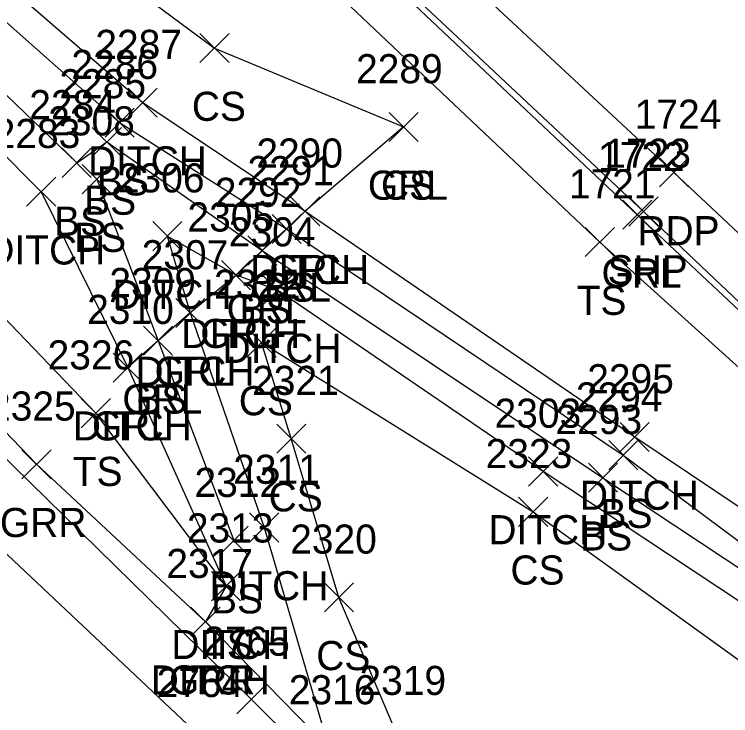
# Model space of a CAD drawing. Extents: x 1647574 to 1652703, y 212895 to 228670.
# Drawn here: x 1648670.85 to 1648720.04, y 227413.3 to 227461.47 of the extents above; entities that cross this region are included whole.
import ezdxf

# ---------------------------------------------------------------- set-up
doc = ezdxf.new("R2010")
doc.units = 0
for name, color, linetype in [('D_A', 7, 'Continuous'), ('D_I', 7, 'Continuous'), ('D_TIC', 7, 'Continuous'), ('DD', 7, 'Continuous'), ('L_A', 7, 'Continuous'), ('L_I', 7, 'Continuous'), ('L_TIC', 7, 'Continuous'), ('LELB', 7, 'Continuous'), ('P_A', 7, 'Continuous'), ('P_I', 7, 'Continuous'), ('P_TIC', 7, 'Continuous'), ('PET', 7, 'Continuous'), ('PSP', 7, 'Continuous'), ('R_A', 7, 'Continuous'), ('R_I', 7, 'Continuous'), ('R_TIC', 7, 'Continuous'), ('RGR', 7, 'Continuous')]:
    doc.layers.add(name, color=color, linetype=linetype)

msp = doc.modelspace()

# ---------------------------------------------------------------- linework, layer by layer
at = {"layer": 'D_TIC'}
for points in [[(1648678.668, 227454.407), (1648680.668, 227456.407)], [(1648680.668, 227454.407), (1648678.668, 227456.407)], [(1648671.688, 227448.29), (1648673.688, 227450.29)], [(1648673.688, 227448.29), (1648671.688, 227450.29)], [(1648689.817, 227446.944), (1648691.817, 227448.944)], [(1648691.817, 227446.944), (1648689.817, 227448.944)], [(1648680.354, 227445.239), (1648682.354, 227447.239)], [(1648682.354, 227445.239), (1648680.354, 227447.239)], [(1648685.075, 227442.554), (1648687.075, 227444.554)], [(1648687.075, 227442.554), (1648685.075, 227444.554)], [(1648687.91, 227441.53), (1648689.91, 227443.53)], [(1648689.91, 227441.53), (1648687.91, 227443.53)], [(1648681.932, 227439.96), (1648683.932, 227441.96)], [(1648683.932, 227439.96), (1648681.932, 227441.96)], [(1648677.631, 227436.205), (1648679.631, 227438.205)], [(1648679.631, 227436.205), (1648677.631, 227438.205)], [(1648712.453, 227431.442), (1648714.453, 227433.442)], [(1648714.453, 227431.442), (1648712.453, 227433.442)], [(1648706.167, 227429.076), (1648708.167, 227431.076)], [(1648708.167, 227429.076), (1648706.167, 227431.076)], [(1648687.005, 227425.227), (1648689.005, 227427.227)], [(1648689.005, 227425.227), (1648687.005, 227427.227)], [(1648684.391, 227421.196), (1648686.391, 227423.196)], [(1648686.391, 227421.196), (1648684.391, 227423.196)], [(1648682.979, 227418.757), (1648684.979, 227420.757)], [(1648684.979, 227418.757), (1648682.979, 227420.757)]]:
    msp.add_lwpolyline(points, dxfattribs=at)
at = {"layer": 'DD'}
for points in [[(1648567.346, 227553.333), (1648570.223, 227556.147), (1648596.039, 227533.3), (1648628.436, 227501.882), (1648658.018, 227474.124), (1648679.668, 227455.407), (1648690.817, 227447.944), (1648713.453, 227432.442), (1648744.751, 227411.459), (1648774.422, 227388.823), (1648782.608, 227379.999), (1648760.626, 227395.219), (1648734.749, 227411.807), (1648707.167, 227430.076), (1648688.91, 227442.53), (1648686.075, 227443.554), (1648681.354, 227446.239), (1648682.932, 227440.96), (1648688.005, 227426.227), (1648692.448, 227411.085)], [(1648567.346, 227553.333), (1648592.358, 227529.266), (1648624.337, 227498.311), (1648653.078, 227469.037), (1648672.688, 227449.29), (1648678.631, 227437.205), (1648685.391, 227422.196), (1648683.979, 227419.757)]]:
    msp.add_lwpolyline(points, dxfattribs=at)
at = {"layer": 'L_TIC'}
for points in [[(1648683.597, 227458.155), (1648685.597, 227460.155)], [(1648685.597, 227458.155), (1648683.597, 227460.155)], [(1648677.081, 227453.032), (1648679.081, 227455.032)], [(1648679.081, 227453.032), (1648677.081, 227455.032)], [(1648696.583, 227452.736), (1648698.583, 227454.736)], [(1648698.583, 227452.736), (1648696.583, 227454.736)], [(1648676.203, 227451.705), (1648678.203, 227453.705)], [(1648678.203, 227451.705), (1648676.203, 227453.705)], [(1648674.133, 227450.269), (1648676.133, 227452.269)], [(1648676.133, 227450.269), (1648674.133, 227452.269)], [(1648675.513, 227449.153), (1648677.513, 227451.153)], [(1648677.513, 227449.153), (1648675.513, 227451.153)], [(1648688.549, 227445.733), (1648690.549, 227447.733)], [(1648690.549, 227445.733), (1648688.549, 227447.733)], [(1648710.057, 227444.83), (1648712.057, 227446.83)], [(1648712.057, 227444.83), (1648710.057, 227446.83)], [(1648686.877, 227444.247), (1648688.877, 227446.247)], [(1648688.877, 227444.247), (1648686.877, 227446.247)], [(1648679.72, 227438.051), (1648681.72, 227440.051)], [(1648681.72, 227438.051), (1648679.72, 227440.051)], [(1648686.821, 227437.933), (1648688.821, 227439.933)], [(1648688.821, 227437.933), (1648686.821, 227439.933)], [(1648675.448, 227433.079), (1648677.448, 227435.079)], [(1648677.448, 227433.079), (1648675.448, 227435.079)], [(1648688.87, 227431.33), (1648690.87, 227433.33)], [(1648690.87, 227431.33), (1648688.87, 227433.33)], [(1648711.668, 227430.195), (1648713.668, 227432.195)], [(1648713.668, 227430.195), (1648711.668, 227432.195)], [(1648710.27, 227428.646), (1648712.27, 227430.646)], [(1648712.27, 227428.646), (1648710.27, 227430.646)], [(1648705.478, 227426.306), (1648707.478, 227428.306)], [(1648707.478, 227426.306), (1648705.478, 227428.306)], [(1648684.914, 227424.325), (1648686.914, 227426.325)], [(1648686.914, 227424.325), (1648684.914, 227426.325)], [(1648684.391, 227421.196), (1648686.391, 227423.196)], [(1648686.391, 227421.196), (1648684.391, 227423.196)], [(1648692.14, 227420.43), (1648694.14, 227422.43)], [(1648694.14, 227420.43), (1648692.14, 227422.43)]]:
    msp.add_lwpolyline(points, dxfattribs=at)
at = {"layer": 'LELB'}
for points in [[(1648774.577, 227389.564), (1648743.287, 227416.755), (1648711.057, 227445.83), (1648678.904, 227476.26), (1648653.936, 227498.583), (1648629.183, 227520.51), (1648599.068, 227550.478), (1648561.985, 227586.585), (1648537.336, 227611.828), (1648495.696, 227652.566), (1648469.806, 227680.635), (1648438.579, 227713.563), (1648409.766, 227744.994), (1648382.958, 227775.491), (1648351.838, 227812.297), (1648319.028, 227851.854)], [(1648685.391, 227422.196), (1648676.448, 227434.079), (1648653.997, 227457.482), (1648622.43, 227483.579), (1648591.456, 227513.122), (1648558.407, 227543.243), (1648525.701, 227574.495), (1648490.449, 227607.705), (1648459.181, 227639.732), (1648423.291, 227671.042), (1648396.89, 227698.593), (1648372.199, 227720.929), (1648349.64, 227747.392), (1648318.233, 227770.206)], [(1648557.515, 227558.902), (1648564.968, 227553.432), (1648569.913, 227558.452), (1648580.441, 227553.074), (1648598.911, 227536.759), (1648632.178, 227504.926), (1648659.98, 227477.367), (1648684.597, 227459.155), (1648697.583, 227453.736)], [(1648570.861, 227553.404), (1648569.637, 227552.186), (1648593.381, 227530.425), (1648625.493, 227499.025), (1648654.222, 227471.402), (1648675.133, 227451.269), (1648677.203, 227452.705), (1648687.877, 227445.247), (1648711.27, 227429.646), (1648742.963, 227408.638)], [(1648570.861, 227553.404), (1648594.803, 227532.123), (1648627.677, 227501.196), (1648656.322, 227473.309), (1648678.081, 227454.032), (1648689.549, 227446.733), (1648712.668, 227431.195), (1648742.963, 227408.638), (1648773.62, 227388.353)], [(1648676.513, 227450.153), (1648680.72, 227439.051), (1648685.914, 227425.325)], [(1648700.712, 227406.969), (1648697.252, 227411.723), (1648693.14, 227421.43), (1648689.87, 227432.33), (1648687.821, 227438.933), (1648706.478, 227427.306), (1648726.383, 227412.975)]]:
    msp.add_lwpolyline(points, dxfattribs=at)
at = {"layer": 'P_TIC'}
for points in [[(1648715.148, 227449.613), (1648717.148, 227451.613)], [(1648717.148, 227449.613), (1648715.148, 227451.613)], [(1648713.056, 227446.93), (1648715.056, 227448.93)], [(1648715.056, 227446.93), (1648713.056, 227448.93)], [(1648686.125, 227413.419), (1648688.125, 227415.419)], [(1648688.125, 227413.419), (1648686.125, 227415.419)]]:
    msp.add_lwpolyline(points, dxfattribs=at)
at = {"layer": 'PET'}
for points in [[(1648813.954, 227358.936), (1648778.044, 227392.689), (1648747.288, 227421.365), (1648716.148, 227450.613), (1648683.895, 227480.61), (1648659.116, 227504.214), (1648636.134, 227525.988), (1648605.632, 227555.477), (1648567.945, 227592.707), (1648543.864, 227616.052), (1648502.527, 227657.191), (1648475.057, 227685.791), (1648444.587, 227717.742), (1648415.435, 227749.693), (1648388.572, 227780.052), (1648357.179, 227817.313), (1648324.353, 227856.66)], [(1648315.17, 227761.114), (1648349.65, 227728.181), (1648382.593, 227697.154), (1648419.403, 227663.054), (1648452.032, 227631.593), (1648489.191, 227596.807), (1648522.695, 227564.838), (1648552.349, 227536.571), (1648584.489, 227506.143), (1648616.974, 227475.478), (1648654.438, 227439.35), (1648683.934, 227411.58), (1648698.744, 227397.704)]]:
    msp.add_lwpolyline(points, dxfattribs=at)
at = {"layer": 'PSP'}
for points in [[(1648862.79, 227349.772), (1648859.77, 227350.009), (1648838.072, 227353.54), (1648813.954, 227358.936), (1648808.767, 227359.651), (1648801.068, 227367.015), (1648799.396, 227367.692), (1648775.507, 227390.23), (1648744.844, 227418.747), (1648714.056, 227447.93), (1648681.623, 227478.355), (1648656.942, 227501.721), (1648633.184, 227523.882), (1648602.918, 227552.912), (1648564.866, 227589.709), (1648540.519, 227613.531), (1648499.098, 227654.744), (1648471.892, 227682.443), (1648441.114, 227715.054), (1648412.287, 227746.761), (1648385.497, 227777.337), (1648354.021, 227814.189), (1648321.056, 227853.92)], [(1648318.358, 227763.007), (1648352.653, 227731.112), (1648385.571, 227699.762), (1648421.79, 227665.61), (1648455.437, 227633.903), (1648491.739, 227599.359), (1648525.609, 227567.102), (1648554.892, 227539.659), (1648587.899, 227508.735), (1648620.045, 227478.677), (1648657.864, 227443.097), (1648687.125, 227414.419), (1648699.803, 227401.852), (1648705.852, 227396.154)]]:
    msp.add_lwpolyline(points, dxfattribs=at)
at = {"layer": 'R_TIC'}
for points in [[(1648696.583, 227452.736), (1648698.583, 227454.736)], [(1648698.583, 227452.736), (1648696.583, 227454.736)], [(1648689.817, 227446.944), (1648691.817, 227448.944)], [(1648691.817, 227446.944), (1648689.817, 227448.944)], [(1648712.629, 227446.707), (1648714.629, 227448.707)], [(1648714.629, 227446.707), (1648712.629, 227448.707)], [(1648688.549, 227445.733), (1648690.549, 227447.733)], [(1648690.549, 227445.733), (1648688.549, 227447.733)], [(1648686.877, 227444.247), (1648688.877, 227446.247)], [(1648688.877, 227444.247), (1648686.877, 227446.247)], [(1648685.075, 227442.554), (1648687.075, 227444.554)], [(1648687.075, 227442.554), (1648685.075, 227444.554)], [(1648681.932, 227439.96), (1648683.932, 227441.96)], [(1648683.932, 227439.96), (1648681.932, 227441.96)], [(1648679.72, 227438.051), (1648681.72, 227440.051)], [(1648681.72, 227438.051), (1648679.72, 227440.051)], [(1648677.631, 227436.205), (1648679.631, 227438.205)], [(1648679.631, 227436.205), (1648677.631, 227438.205)], [(1648671.368, 227429.569), (1648673.368, 227431.569)], [(1648673.368, 227429.569), (1648671.368, 227431.569)], [(1648682.979, 227418.757), (1648684.979, 227420.757)], [(1648684.979, 227418.757), (1648682.979, 227420.757)]]:
    msp.add_lwpolyline(points, dxfattribs=at)
at = {"layer": 'RGR'}
for points in [[(1648799.396, 227367.692), (1648775.209, 227390.092), (1648744.666, 227418.577), (1648713.629, 227447.707), (1648681.406, 227478.095), (1648656.746, 227501.396), (1648632.98, 227523.33), (1648602.406, 227552.124), (1648564.557, 227589.406), (1648540.303, 227613.502), (1648498.82, 227654.38), (1648471.444, 227682.066), (1648440.86, 227714.66), (1648411.806, 227746.436), (1648384.967, 227776.708), (1648353.625, 227813.747), (1648320.767, 227853.114)], [(1648697.722, 227405.66), (1648692.448, 227411.085), (1648683.979, 227419.757), (1648672.368, 227430.569), (1648663.534, 227439.762), (1648649.677, 227452.686), (1648619.083, 227481.01), (1648588.855, 227509.073), (1648555.338, 227540.277), (1648523.339, 227570.453), (1648487.379, 227604.542), (1648455.361, 227634.996), (1648420.16, 227668.084), (1648392.977, 227694.219), (1648369.015, 227716.998), (1648345.956, 227742.519)], [(1648697.583, 227453.736), (1648690.817, 227447.944), (1648689.549, 227446.733), (1648687.877, 227445.247), (1648686.075, 227443.554), (1648682.932, 227440.96), (1648680.72, 227439.051), (1648678.631, 227437.205)]]:
    msp.add_lwpolyline(points, dxfattribs=at)

# ---------------------------------------------------------------- texts
at = {"layer": 'D_A'}
for p in [(1648675.905, 227450.407), (1648668.924, 227444.29), (1648687.053, 227442.944), (1648677.59, 227441.239), (1648682.311, 227438.554), (1648685.147, 227437.53), (1648679.169, 227435.96), (1648674.867, 227432.205), (1648709.689, 227427.442), (1648703.403, 227425.076), (1648684.242, 227421.227), (1648681.628, 227417.196), (1648680.216, 227414.757)]:
    msp.add_text('DITCH', height=2, dxfattribs=at).set_placement(p)
at = {"layer": 'D_I'}
for s, p in [('2287', (1648676.409, 227458.407)), ('2283', (1648669.428, 227452.29)), ('2290', (1648687.471, 227450.944)), ('2306', (1648677.96, 227449.239)), ('2305', (1648682.737, 227446.554)), ('2304', (1648685.572, 227445.53)), ('2307', (1648679.594, 227443.96)), ('2310', (1648675.852, 227440.205)), ('2295', (1648710.193, 227435.442)), ('2303', (1648703.829, 227433.076)), ('2311', (1648685.879, 227429.227)), ('2313', (1648682.698, 227425.196)), ('2317', (1648681.287, 227422.757)), ('2316', (1648689.7, 227414.085))]:
    msp.add_text(s, height=2, dxfattribs=at).set_placement(p)
at = {"layer": 'L_A'}
for s, p in [('CS', (1648683.038, 227454.155)), ('BS', (1648676.522, 227449.032)), ('CS', (1648696.024, 227448.736)), ('BS', (1648675.644, 227447.705)), ('BS', (1648673.574, 227446.269)), ('BS', (1648674.954, 227445.153)), ('BS', (1648687.99, 227441.733)), ('TS', (1648709.467, 227440.83)), ('BS', (1648686.318, 227440.247)), ('BS', (1648679.161, 227434.051)), ('CS', (1648686.262, 227433.933)), ('TS', (1648674.857, 227429.079)), ('CS', (1648688.311, 227427.33)), ('BS', (1648711.109, 227426.195)), ('BS', (1648709.711, 227424.646)), ('CS', (1648704.919, 227422.306)), ('BS', (1648684.354, 227420.325)), ('TS', (1648683.801, 227417.196)), ('CS', (1648691.581, 227416.43))]:
    msp.add_text(s, height=2, dxfattribs=at).set_placement(p)
at = {"layer": 'L_I'}
for s, p in [('2286', (1648674.766, 227457.032)), ('2289', (1648694.316, 227456.736)), ('2285', (1648673.943, 227455.705)), ('2284', (1648671.873, 227454.269)), ('2308', (1648673.175, 227453.153)), ('2291', (1648686.856, 227449.733)), ('1721', (1648708.932, 227448.83)), ('2292', (1648684.617, 227448.247)), ('2309', (1648677.374, 227442.051)), ('2322', (1648684.561, 227441.933)), ('2326', (1648673.133, 227437.079)), ('2321', (1648687.177, 227435.33)), ('2294', (1648709.409, 227434.195)), ('2293', (1648708.01, 227432.646)), ('2323', (1648703.218, 227430.306)), ('2312', (1648683.221, 227428.325)), ('2313', (1648682.698, 227425.196)), ('2320', (1648689.794, 227424.43)), ('2319', (1648694.552, 227414.723))]:
    msp.add_text(s, height=2, dxfattribs=at).set_placement(p)
at = {"layer": 'P_A'}
for s, p in [('RDP', (1648713.637, 227445.613)), ('SHP', (1648711.591, 227442.93))]:
    msp.add_text(s, height=2, dxfattribs=at).set_placement(p)
at = {"layer": 'P_I'}
for s, p in [('1724', (1648713.456, 227453.613)), ('1723', (1648711.363, 227450.93)), ('2765', (1648683.818, 227417.419)), ('2764', (1648680.627, 227414.58))]:
    msp.add_text(s, height=2, dxfattribs=at).set_placement(p)
at = {"layer": 'R_A'}
for s, p in [('GRL', (1648695.127, 227448.736)), ('GRL', (1648688.36, 227442.944)), ('GRL', (1648711.172, 227442.707)), ('GRL', (1648687.093, 227441.733)), ('GRL', (1648685.42, 227440.247)), ('GRL', (1648683.618, 227438.554)), ('GRL', (1648680.475, 227435.96)), ('GRL', (1648678.264, 227434.051)), ('GRL', (1648676.174, 227432.205)), ('GRR', (1648669.857, 227425.569)), ('GRR', (1648681.467, 227414.757))]:
    msp.add_text(s, height=2, dxfattribs=at).set_placement(p)
at = {"layer": 'R_I'}
for s, p in [('2289', (1648694.316, 227456.736)), ('2290', (1648687.471, 227450.944)), ('1722', (1648710.936, 227450.707)), ('2291', (1648686.856, 227449.733)), ('2292', (1648684.617, 227448.247)), ('2305', (1648682.737, 227446.554)), ('2307', (1648679.594, 227443.96)), ('2309', (1648677.374, 227442.051)), ('2310', (1648675.852, 227440.205)), ('2325', (1648669.109, 227433.569)), ('2317', (1648681.287, 227422.757)), ('2316', (1648689.7, 227414.085))]:
    msp.add_text(s, height=2, dxfattribs=at).set_placement(p)

doc.saveas('drawing.dxf')
